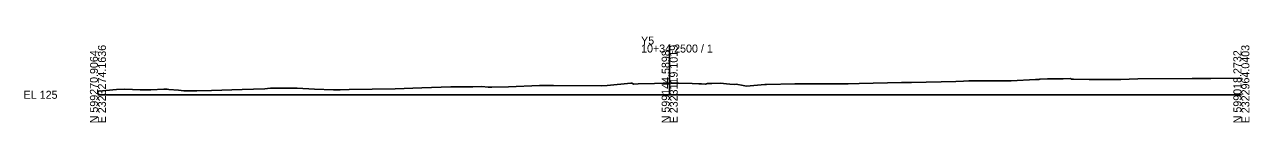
# Model space of a CAD drawing. Extents: x -26 to 4603, y 1490 to 2017.
# Drawn here: x 4174.3 to 4602.8, y 1490.3 to 1520.4 of the extents above; entities that cross this region are included whole.
import ezdxf

# ---------------------------------------------------------------- set-up
doc = ezdxf.new("R2010")
doc.units = 0
for name, color, linetype in [('Exist CMT Pavement', 7, 'Continuous'), ('Exist Cross Section Cell', 7, 'Continuous'), ('Exist XS Center Line Elevation Label', 7, 'Continuous'), ('Exist XS Ground Line', 7, 'Continuous'), ('Prop XS Earthwork Shape', 7, 'Continuous')]:
    doc.layers.add(name, color=color, linetype=linetype)

msp = doc.modelspace()

# ---------------------------------------------------------------- linework, layer by layer
at = {"layer": 'Exist CMT Pavement'}
for points in [[(4399.9, 1504.04), (4399.9, 1504.14), (4400, 1504.14), (4400, 1504.04)], [(4400, 1504.04), (4400, 1504.14), (4400.1, 1504.14), (4400.1, 1504.01)]]:
    msp.add_lwpolyline(points, dxfattribs=at)
at = {"layer": 'Exist Cross Section Cell'}
for p, q in [((4400, 1500), (4400, 1517.6)), ((4200, 1500), (4400, 1500)), ((4400, 1500), (4600, 1500))]:
    msp.add_line(p, q, dxfattribs=at)
at = {"layer": 'Exist XS Ground Line'}
msp.add_lwpolyline([(4200, 1501.28), (4200.35, 1501.28), (4206.46, 1501.8), (4209.16, 1501.94), (4212.08, 1501.81), (4214.77, 1501.68), (4218.48, 1501.68), (4223.04, 1501.91), (4224.26, 1501.91), (4224.82, 1501.83), (4228.21, 1501.56), (4230, 1501.43), (4234.58, 1501.43), (4239.67, 1501.49), (4250.49, 1501.8), (4258.36, 1502.11), (4259.27, 1502.16), (4260.42, 1502.36), (4265.03, 1502.31), (4268.54, 1502.32), (4269.74, 1502.31), (4275.8, 1501.92), (4282.38, 1501.74), (4284.75, 1501.75), (4287.93, 1501.8), (4303.94, 1502.09), (4313.26, 1502.48), (4316.68, 1502.56), (4323.44, 1502.74), (4323.84, 1502.74), (4331.09, 1502.75), (4334.31, 1502.86), (4336.53, 1502.71), (4337.79, 1502.67), (4343.64, 1502.83), (4354.51, 1503.23), (4357.02, 1503.27), (4359.32, 1503.27), (4376.01, 1503.17), (4378.15, 1503.2), (4386.39, 1504.07), (4386.72, 1504.08), (4387.51, 1503.77), (4388.96, 1503.81), (4394.71, 1503.94), (4397.71, 1504.01), (4398.09, 1504.02), (4398.98, 1504.05), (4400, 1504.04), (4400.34, 1503.94), (4400.37, 1504.07), (4403.09, 1504.05), (4407.89, 1503.92), (4410.24, 1503.86), (4411.17, 1503.81), (4412.53, 1503.68), (4413.28, 1503.98), (4414.23, 1504), (4414.7, 1503.98), (4417.72, 1504.02), (4421.04, 1503.68), (4422.56, 1503.6), (4423.27, 1503.69), (4425.74, 1503.2), (4426.89, 1503), (4432.05, 1503.48), (4433.34, 1503.62), (4433.91, 1503.62), (4443.75, 1503.78), (4447.76, 1503.78), (4462.4, 1503.86), (4466.34, 1503.93), (4481.05, 1504.3), (4484.6, 1504.35), (4500.11, 1504.69), (4502.76, 1504.76), (4504.66, 1504.87), (4517.27, 1504.9), (4519.41, 1504.83), (4527.92, 1505.4), (4528.63, 1505.4), (4529.1, 1505.4), (4529.46, 1505.51), (4532.22, 1505.55), (4537.6, 1505.62), (4540.23, 1505.67), (4540.56, 1505.46), (4541.25, 1505.51), (4546.8, 1505.3), (4557.8, 1505.39), (4560.73, 1505.42), (4563.82, 1505.53), (4582.83, 1505.75), (4586.51, 1505.75), (4589.37, 1505.74), (4600, 1505.87)], dxfattribs=at)
at = {"layer": 'Prop XS Earthwork Shape'}
for points in [[(4400, 1504.14), (4400, 1504.04), (4399.9, 1504.04), (4399.9, 1504.14)], [(4400, 1504.04), (4400.1, 1504.01), (4400.1, 1504.14), (4400, 1504.14)]]:
    msp.add_lwpolyline(points, close=True, dxfattribs=at)

# ---------------------------------------------------------------- texts
at = {"layer": 'Exist Cross Section Cell'}
for s, p in [('E 2323274.1636', (4202.8, 1490)), ('E 2323119.1019', (4402.8, 1490)), ('E 2322964.0403', (4602.8, 1490)), ('N 599270.9064', (4200, 1490)), ('N 599144.5898', (4400, 1490)), ('N 599018.2732', (4600, 1490))]:
    msp.add_text(s, height=2.8, rotation=90, dxfattribs=at).set_placement(p)
for s, p in [('Y5', (4390, 1517.6)), ('10+34.2500 / 1', (4390, 1514.8)), ('EL 125', (4174, 1498.6))]:
    msp.add_text(s, height=2.8, dxfattribs=at).set_placement(p)
at = {"layer": 'Exist XS Center Line Elevation Label'}
msp.add_text('129.04', height=0.2, dxfattribs=at).set_placement((4399.61, 1502.04))

doc.saveas('drawing.dxf')
